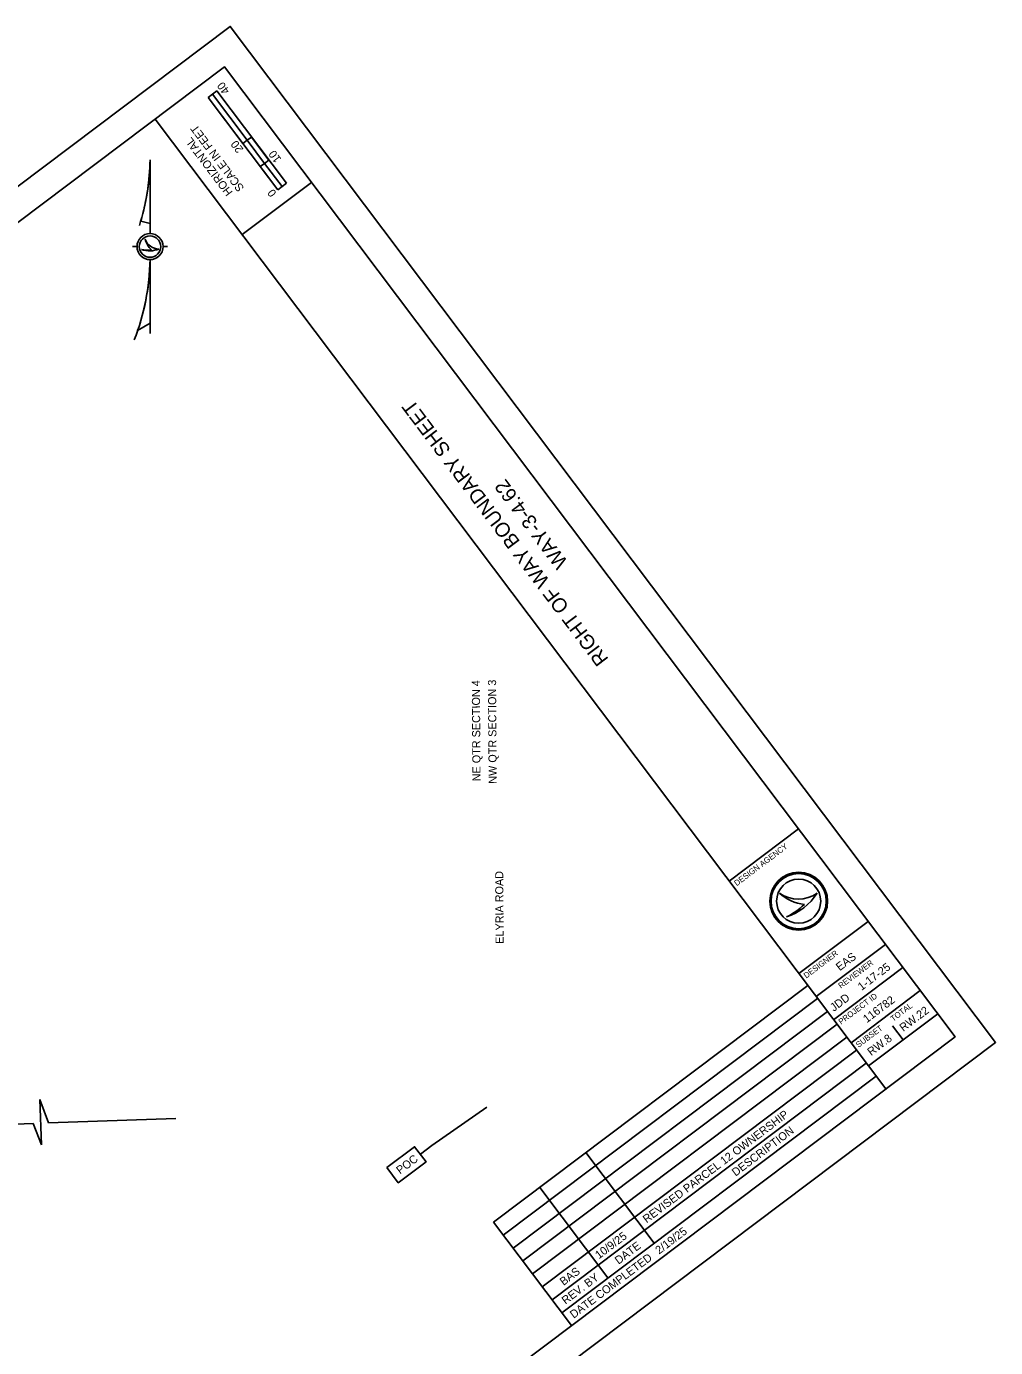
# Model space of a CAD drawing. Extents: x 120947 to 121755, y 462235 to 462996.
# Drawn here: x 121419.5 to 121754.7, y 462538.5 to 462995.5 of the extents above; entities that cross this region are included whole.
import ezdxf

# ---------------------------------------------------------------- set-up
doc = ezdxf.new("R2010")
doc.units = 0
for name, color, linetype in [('DV_X_Property_Line', 7, 'Continuous'), ('DV_X_Section_VMS_Line', 7, 'Continuous'), ('SV_P_Control_Cells_Set', 7, 'Continuous'), ('SV_X_Mon_Cells_Found', 7, 'Continuous')]:
    doc.layers.add(name, color=color, linetype=linetype)

msp = doc.modelspace()

# ---------------------------------------------------------------- linework, layer by layer
at = {"layer": 'DV_X_Property_Line'}
for p, q in [((121485.35, 462973.26), (121482.36, 462971)), ((121482.36, 462971), (121483.85, 462972.13)), ((121506.42, 462939.05), (121482.36, 462971)), ((121494.39, 462955.03), (121482.36, 462971)), ((121483.85, 462972.13), (121483.86, 462972.14)), ((121483.86, 462972.14), (121495.89, 462956.16)), ((121485.35, 462973.26), (121509.42, 462941.31)), ((121495.89, 462956.16), (121494.39, 462955.03)), ((121497.37, 462957.27), (121495.88, 462956.15)), ((121495.88, 462956.15), (121501.9, 462948.16)), ((121503.39, 462949.28), (121497.37, 462957.27)), ((121462.26, 462923.87), (121462.26, 462949.37)), ((121501.9, 462948.16), (121500.4, 462947.04)), ((121500.4, 462947.04), (121506.42, 462939.05)), ((121501.9, 462948.16), (121503.39, 462949.28)), ((121507.91, 462940.17), (121501.9, 462948.16)), ((121509.42, 462941.31), (121506.42, 462939.05)), ((121506.42, 462939.05), (121507.91, 462940.17)), ((121459.07, 462928.18), (121462.26, 462927.31)), ((121456.16, 462919.37), (121457.76, 462919.37)), ((121466.76, 462919.37), (121468.36, 462919.37)), ((121462.26, 462889.37), (121462.26, 462914.87)), ((121462.26, 462892.87), (121457.96, 462890.3)), ((121679.96, 462695.68), (121679.96, 462695.68)), ((121692.97, 462695.68), (121692.97, 462695.68)), ((121686.6, 462692.93), (121686.6, 462692.93)), ((121682.37, 462687.48), (121682.37, 462687.48)), ((121722.7, 462645), (121719.09, 462649.79))]:
    msp.add_line(p, q, dxfattribs=at)
for points in [[(121459.05, 462928.18), (121459.07, 462928.18), (121462.26, 462927.31), (121462.26, 462949.37)], [(121457.96, 462890.3), (121462.26, 462892.87), (121462.26, 462914.87)]]:
    msp.add_lwpolyline(points, dxfattribs=at)
for centre, radius in [((121462.26, 462919.37), 4.5), ((121462.26, 462919.37), 3.7), ((121686.6, 462692.93), 10), ((121686.6, 462692.93), 9.54), ((121686.6, 462692.93), 9.54), ((121686.6, 462692.93), 7.64)]:
    msp.add_circle(centre, radius, dxfattribs=at)
for centre, radius, start, end in [((121383.41, 462950.48), 78.85, 342.4153, 359.1947), ((121383.41, 462950.48), 78.85, 343.5754, 359.1947), ((121465.4, 462923.63), 5.1, 199.1575, 269.3709), ((121467.58, 462923.55), 7.17, 192.8556, 227.3141), ((121383.41, 462915.98), 78.85, 338.5054, 359.1947), ((121383.41, 462915.98), 78.85, 340.9936, 359.1947), ((121462.03, 462926.95), 9.05, 252.4874, 291.486), ((121461.15, 462929.6), 11.43, 260.7277, 277.8734), ((121686.46, 462705.28), 11.6, 235.9088, 235.9151), ((121690.48, 462707.62), 15.91, 228.6211, 228.6253), ((121686.46, 462705.28), 11.6, 235.9151, 304.1489), ((121690.48, 462707.62), 15.91, 228.6253, 263.0778), ((121675.96, 462706.7), 20.26, 288.4408, 327.0664), ((121671.08, 462710.14), 25.32, 296.4827, 313.6504), ((121671.08, 462710.14), 25.32, 296.4795, 296.4827), ((121675.96, 462706.7), 20.26, 288.4359, 288.4408)]:
    msp.add_arc(centre, radius, start, end, dxfattribs=at)
at = {"layer": 'DV_X_Section_VMS_Line'}
for p, q in [((121716.73, 462627.99), (121464.07, 462963.49)), ((121494.14, 462923.55), (121518.11, 462941.59)), ((121662.59, 462699.88), (121686.55, 462717.93)), ((121686.65, 462667.93), (121710.61, 462685.97)), ((121692.67, 462659.94), (121716.63, 462677.99)), ((121698.68, 462651.95), (121722.65, 462670)), ((121704.7, 462643.96), (121728.66, 462662.01)), ((121710.71, 462635.97), (121734.68, 462654.02))]:
    msp.add_line(p, q, dxfattribs=at)
msp.add_lwpolyline([(120976.79, 462596.52), (121488.03, 462981.53), (121740.69, 462646.03), (121229.45, 462261.02)], close=True, dxfattribs=at)
at = {"layer": 'SV_P_Control_Cells_Set'}
msp.add_lwpolyline([(121211.5, 462234.99), (121754.7, 462644.06), (121490, 462995.54), (120946.81, 462586.46)], close=True, dxfattribs=at)
at = {"layer": 'SV_X_Mon_Cells_Found'}
for p, q in [((121581.09, 462581.92), (121689.78, 462663.77)), ((121584.45, 462577.44), (121693.15, 462659.3)), ((121587.82, 462572.97), (121696.52, 462654.83)), ((121591.19, 462568.5), (121699.88, 462650.35)), ((121594.56, 462564.02), (121703.25, 462645.88)), ((121597.93, 462559.55), (121706.62, 462641.41)), ((121601.3, 462555.08), (121709.99, 462636.93)), ((121604.67, 462550.6), (121713.36, 462632.46)), ((121716.73, 462627.99), (121716.73, 462627.99)), ((121424.67, 462608.61), (121424.11, 462624.35)), ((121427.16, 462616.25), (121424.11, 462624.35)), ((121471.24, 462617.82), (121427.16, 462616.25)), ((121421.79, 462616.06), (121377.55, 462614.49)), ((121424.67, 462608.61), (121421.79, 462616.06)), ((121613.04, 462605.98), (121636.62, 462574.67)), ((121597.06, 462593.95), (121620.64, 462562.63)), ((121581.09, 462581.92), (121608.04, 462546.13))]:
    msp.add_line(p, q, dxfattribs=at)
msp.add_lwpolyline([(121555.75, 462605.41), (121559.74, 462608.41), (121578.69, 462621.64)], dxfattribs=at)
msp.add_lwpolyline([(121544.16, 462600.76), (121553.78, 462608.02), (121557.71, 462602.8), (121548.09, 462595.55)], close=True, dxfattribs=at)

# ---------------------------------------------------------------- texts
at = {"layer": 'DV_X_Property_Line'}
for s, height, rotation, p in [('40', 2.8, 126.9831, (121489.98, 462973.3)), ('SCALE IN FEET', 2.8, 126.9831, (121494.95, 462939.69)), ('HORIZONTAL', 2.8, 126.9831, (121491, 462938.19)), ('20', 2.8, 126.9831, (121494.7, 462953.07)), ('10', 2.8, 126.9831, (121507.79, 462949.66)), ('0', 2.8, 126.9831, (121506.15, 462937.88)), ('RIGHT OF WAY BOUNDARY SHEET', 5, 126.9831, (121621.04, 462776.66)), ('WAY-3-4.62', 5, 126.9831, (121607.01, 462810.24)), ('DESIGN AGENCY', 2, 36.9831, (121665.19, 462698.08)), ('DESIGNER', 2, 36.9831, (121689.25, 462666.13)), ('EAS', 2.8, 36.9831, (121700.78, 462668.68)), ('REVIEWER', 2, 36.9831, (121701.21, 462662.62)), ('1-17-25', 2.8, 36.9831, (121708.35, 462661.86)), ('JDD', 2.8, 36.9831, (121698.76, 462654.64)), ('PROJECT ID', 2, 36.9831, (121701.29, 462650.16)), ('116782', 2.8, 36.9831, (121710.16, 462650.7)), ('TOTAL', 2, 36.9831, (121719.28, 462651.19)), ('RW.22', 2.8, 36.9831, (121722.78, 462647.69)), ('SUBSET', 2, 36.9831, (121707.3, 462642.17)), ('RW.8', 2.8, 36.9831, (121711.67, 462639.32))]:
    msp.add_text(s, height=height, rotation=rotation, dxfattribs=at).set_placement(p)
at = {"layer": 'SV_X_Mon_Cells_Found'}
for s, rotation, p in [('NE QTR SECTION 4', 90.3623, (121576.57, 462734.43)), ('NW QTR SECTION 3', 90.3623, (121582.17, 462733.58)), ('ELYRIA ROAD', 90.3623, (121584.58, 462678.21)), ('REVISED PARCEL 12 OWNERSHIP            ', 36.9831, (121634.01, 462581.46)), ('DESCRIPTION', 36.9831, (121664.79, 462597.63)), ('POC', 36.9831, (121548.73, 462598.37)), (' 10/9/25', 36.9831, (121616.68, 462568.41)), ('2/19/25                             ', 36.9831, (121638.31, 462570.68)), ('DATE', 36.9831, (121624.32, 462567.16)), ('DATE COMPLETED', 36.9831, (121608.79, 462548.45)), ('BAS', 36.9831, (121605.28, 462559.83)), ('REV. BY', 36.9831, (121605.96, 462553.33))]:
    msp.add_text(s, height=2.8, rotation=rotation, dxfattribs=at).set_placement(p)

doc.saveas('drawing.dxf')
